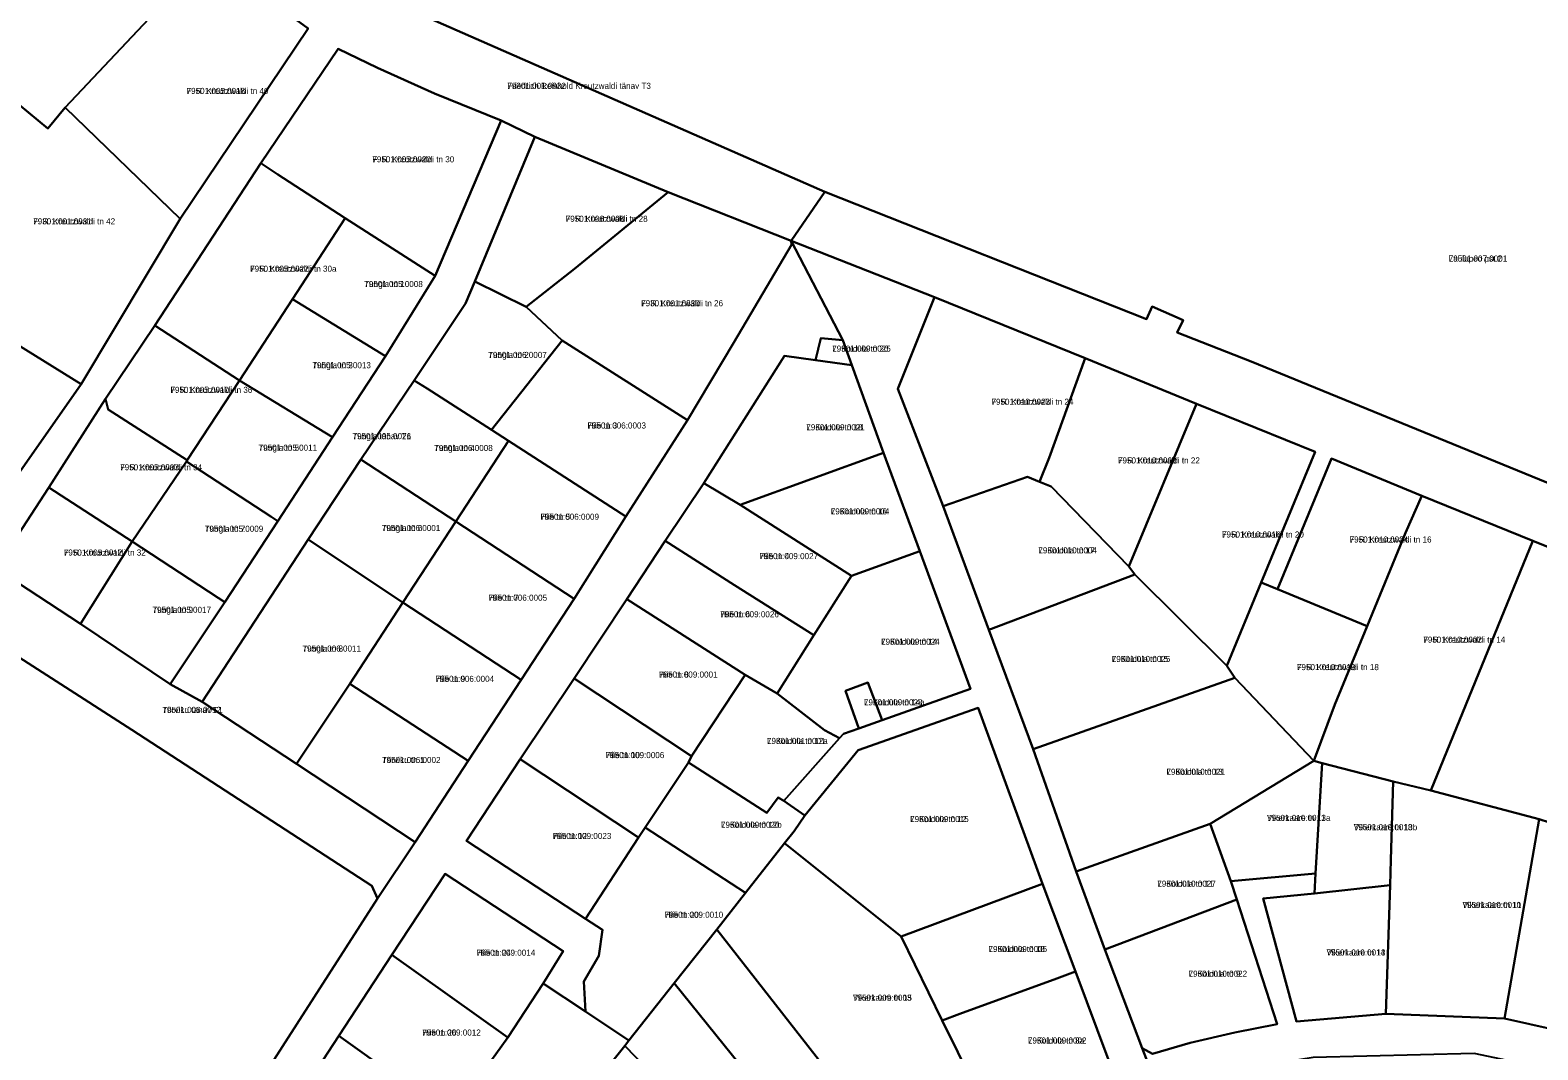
# Model space of a CAD drawing. Extents: x 643847 to 663718, y 6468443 to 6482775.
# Drawn here: x 657706.6 to 658080, y 6474676.3 to 6474928.9 of the extents above; entities that cross this region are included whole.
import ezdxf

# ---------------------------------------------------------------- set-up
doc = ezdxf.new("R2010")
doc.units = 0
for name, color, linetype in [('L_AADRESS', 7, 'Continuous'), ('PIIR', 7, 'Continuous'), ('TUNNUS', 7, 'Continuous')]:
    doc.layers.add(name, color=color, linetype=linetype)

msp = doc.modelspace()

# ---------------------------------------------------------------- linework, layer by layer
at = {"layer": 'PIIR'}
for points in [[(658368.95, 6474713.1), (658360.66, 6474702.37), (658267.33, 6474740.81), (658142.75, 6474792.04), (658009.02, 6474846.81), (657990.7, 6474854.01), (657992.16, 6474857.05), (657984.47, 6474860.4), (657983.07, 6474857.31), (657903.43, 6474888.85), (657797.5, 6474935.34), (657789.25, 6474936.69), (657954.47, 6475040.78), (658054.62, 6474961.35), (658120.68, 6474909.93), (658236.64, 6474817.54)], [(657657.15, 6474928.51), (657631.83, 6474952.27), (657635.14, 6474954.7), (657640.69, 6474958.88), (657651.21, 6474965.02), (657664.12, 6474971.48), (657667.65, 6474973.25), (657692.56, 6474996.42), (657695.37, 6474997.08), (657698.35, 6474996.6), (657712.52, 6474987.7), (657751.18, 6474947.87), (657715.23, 6474909.77), (657710.96, 6474904.51), (657691.74, 6474920.38), (657684.32, 6474903.66), (657681.91, 6474905.58)], [(657753.83, 6474945.17), (657775.42, 6474929.36), (657743.72, 6474882.17), (657715.23, 6474909.77), (657751.18, 6474947.87)], [(657782.86, 6474924.32), (657792.63, 6474919.61), (657806.7, 6474913.25), (657823.21, 6474906.52), (657806.88, 6474868.01), (657784.64, 6474882.35), (657775.21, 6474888.43), (657767.93, 6474893.13), (657763.7, 6474895.95)], [(657715.23, 6474909.77), (657743.72, 6474882.17), (657719.23, 6474841.21), (657668.42, 6474872.63), (657681.91, 6474905.58), (657684.32, 6474903.66), (657691.74, 6474920.38), (657710.96, 6474904.51)], [(657806.88, 6474868.01), (657823.21, 6474906.52), (657831.55, 6474902.47), (657816.68, 6474866.66), (657814.4, 6474861.17), (657801.72, 6474842.12), (657788.45, 6474822.54), (657775.46, 6474802.68), (657749.17, 6474762.49), (657741.29, 6474766.89), (657754.78, 6474787.19), (657767.89, 6474807.29), (657781.43, 6474828.06), (657794.55, 6474848.17)], [(657829.46, 6474860.39), (657816.68, 6474866.66), (657831.55, 6474902.47), (657864.58, 6474888.75), (657841.43, 6474869.77)], [(657763.7, 6474895.95), (657767.93, 6474893.13), (657775.21, 6474888.43), (657784.64, 6474882.35), (657771.52, 6474862.25), (657758.4, 6474842.14), (657737.47, 6474855.75)], [(657841.43, 6474869.77), (657864.58, 6474888.75), (657895.09, 6474876.69), (657895.12, 6474875.76), (657880.89, 6474851.48), (657869.4, 6474832.27), (657838.35, 6474852.04), (657829.46, 6474860.39)], [(657794.55, 6474848.17), (657771.52, 6474862.25), (657784.64, 6474882.35), (657806.88, 6474868.01)], [(657690.64, 6474800.49), (657682.76, 6474805.73), (657644.4, 6474800.63), (657637.48, 6474852.67), (657668.42, 6474872.63), (657719.23, 6474841.21)], [(657814.4, 6474861.17), (657816.68, 6474866.66), (657829.46, 6474860.39), (657838.35, 6474852.04), (657820.86, 6474829.86), (657804.88, 6474840.1), (657801.72, 6474842.12)], [(657967.91, 6474847.62), (657959.01, 6474822.92), (657956.55, 6474817.03), (657953.62, 6474818.24), (657932.75, 6474810.97), (657921.48, 6474840), (657930.59, 6474862.78)], [(657781.43, 6474828.06), (657758.4, 6474842.14), (657771.52, 6474862.25), (657794.55, 6474848.17)], [(657737.47, 6474855.75), (657758.4, 6474842.14), (657745.49, 6474822.33), (657725.89, 6474834.9), (657725.25, 6474837.53)], [(657854.12, 6474808.39), (657825.08, 6474827.17), (657820.86, 6474829.86), (657838.35, 6474852.04), (657869.4, 6474832.27)], [(657902.39, 6474852.63), (657907.85, 6474852.06), (657910.12, 6474845.89), (657901.07, 6474847.15)], [(657917.96, 6474824.17), (657882.4, 6474811.33), (657873.42, 6474816.68), (657893.39, 6474848.24), (657901.07, 6474847.15), (657910.12, 6474845.89)], [(657995.48, 6474836.36), (657978.72, 6474796.01), (657959.48, 6474815.81), (657956.55, 6474817.03), (657959.01, 6474822.92), (657967.91, 6474847.62)], [(657767.89, 6474807.29), (657766.22, 6474808.38), (657745.29, 6474822.04), (657745.49, 6474822.33), (657758.4, 6474842.14), (657781.43, 6474828.06)], [(657801.72, 6474842.12), (657804.88, 6474840.1), (657820.86, 6474829.86), (657825.08, 6474827.17), (657812.02, 6474807.16), (657788.45, 6474822.54)], [(657711.22, 6474815.61), (657725.25, 6474837.53), (657725.89, 6474834.9), (657745.49, 6474822.33), (657745.29, 6474822.04), (657731.82, 6474802.19)], [(657995.48, 6474836.36), (658024.82, 6474824.43), (658011.47, 6474792.07), (658002.95, 6474771.42), (657980.22, 6474794.01), (657978.72, 6474796.01)], [(657841.32, 6474788.03), (657812.02, 6474807.16), (657825.08, 6474827.17), (657854.12, 6474808.39)], [(657754.78, 6474787.19), (657753.11, 6474788.28), (657731.82, 6474802.19), (657745.29, 6474822.04), (657766.22, 6474808.38), (657767.89, 6474807.29)], [(657788.45, 6474822.54), (657812.02, 6474807.16), (657798.89, 6474787.06), (657775.46, 6474802.68)], [(657926.97, 6474799.81), (657910, 6474793.69), (657882.4, 6474811.33), (657917.96, 6474824.17)], [(658051.24, 6474813.54), (658047.26, 6474804.34), (658037.72, 6474781.23), (658015.53, 6474790.39), (658028.88, 6474822.75)], [(657932.75, 6474810.97), (657953.62, 6474818.24), (657956.55, 6474817.03), (657959.48, 6474815.81), (657978.72, 6474796.01), (657980.22, 6474794.01), (657944.02, 6474780.31)], [(657711.22, 6474815.61), (657731.82, 6474802.19), (657719.04, 6474781.84), (657698.09, 6474795.51)], [(657863.88, 6474802.34), (657873.42, 6474816.68), (657882.4, 6474811.33), (657910, 6474793.69), (657900.72, 6474779), (657881.03, 6474791.38), (657871.83, 6474797.29)], [(658078.76, 6474802.34), (658053.51, 6474740.48), (658044.18, 6474742.72), (658026.62, 6474747.31), (658024.52, 6474747.88), (658029.7, 6474761.8), (658037.72, 6474781.23), (658047.26, 6474804.34), (658051.24, 6474813.54)], [(657828.2, 6474767.93), (657798.89, 6474787.06), (657812.02, 6474807.16), (657841.32, 6474788.03)], [(657801.97, 6474727.72), (657792.61, 6474713.76), (657791.23, 6474716.92), (657731.79, 6474755.58), (657674.33, 6474792.51), (657645.98, 6474788.74), (657566.4, 6474778.14), (657565.29, 6474786.3), (657644.93, 6474796.66), (657644.4, 6474800.63), (657682.76, 6474805.73), (657690.64, 6474800.49), (657698.09, 6474795.51), (657719.04, 6474781.84), (657741.29, 6474766.89), (657749.17, 6474762.49), (657772.52, 6474747.12)], [(657741.29, 6474766.89), (657719.04, 6474781.84), (657731.82, 6474802.19), (657753.11, 6474788.28), (657754.78, 6474787.19)], [(657749.17, 6474762.49), (657775.46, 6474802.68), (657798.89, 6474787.06), (657785.78, 6474766.96), (657772.52, 6474747.12)], [(657863.88, 6474802.34), (657871.83, 6474797.29), (657881.03, 6474791.38), (657900.72, 6474779), (657891.62, 6474764.54), (657883.64, 6474769.14), (657854.38, 6474787.94)], [(657926.97, 6474799.81), (657939.46, 6474765.69), (657917.64, 6474757.95), (657914.02, 6474767.28), (657908.55, 6474765.21), (657911.85, 6474755.87), (657908.07, 6474754.58), (657907.02, 6474753.49), (657903.29, 6474755.49), (657891.62, 6474764.54), (657900.72, 6474779), (657910, 6474793.69)], [(658106.56, 6474791.26), (658082.9, 6474732.57), (658080.32, 6474733.4), (658053.51, 6474740.48), (658078.76, 6474802.34)], [(657792.61, 6474713.76), (657685.52, 6474547), (657625.76, 6474585.87), (657621.21, 6474620.11), (657588, 6474615.68), (657566.4, 6474778.14), (657645.98, 6474788.74), (657674.33, 6474792.51), (657731.79, 6474755.58), (657791.23, 6474716.92)], [(657944.02, 6474780.31), (657980.22, 6474794.01), (658002.95, 6474771.42), (658004.95, 6474768.4), (657954.99, 6474750.73)], [(658015.53, 6474790.39), (658037.72, 6474781.23), (658029.7, 6474761.8), (658024.52, 6474747.88), (658004.95, 6474768.4), (658002.95, 6474771.42), (658011.47, 6474792.07)], [(657815.09, 6474747.83), (657785.78, 6474766.96), (657798.89, 6474787.06), (657828.2, 6474767.93)], [(657854.38, 6474787.94), (657883.64, 6474769.14), (657870.41, 6474749.05), (657841.29, 6474768.23)], [(657772.52, 6474747.12), (657785.78, 6474766.96), (657815.09, 6474747.83), (657801.97, 6474727.72)], [(657841.29, 6474768.23), (657870.41, 6474749.05), (657869.61, 6474747.42), (657858.9, 6474731.35), (657857.26, 6474728.84), (657827.95, 6474748.27)], [(657870.41, 6474749.05), (657883.64, 6474769.14), (657891.62, 6474764.54), (657903.29, 6474755.49), (657907.02, 6474753.49), (657893.25, 6474737.94), (657891.87, 6474738.81), (657889.03, 6474734.98), (657869.61, 6474747.42)], [(657917.64, 6474757.95), (657911.85, 6474755.87), (657908.55, 6474765.21), (657914.02, 6474767.28)], [(657954.99, 6474750.73), (658004.95, 6474768.4), (658024.52, 6474747.88), (657998.88, 6474732.25), (657965.68, 6474720.42)], [(657957.36, 6474717.42), (657922.35, 6474704.37), (657893.43, 6474727.47), (657895.78, 6474730.48), (657898.45, 6474734.34), (657911.63, 6474750.5), (657941.37, 6474761.01)], [(657857.26, 6474728.84), (657844.13, 6474708.75), (657814.68, 6474728.01), (657827.95, 6474748.27)], [(657898.45, 6474734.34), (657895.78, 6474730.48), (657893.43, 6474727.47), (657883.74, 6474715.13), (657858.9, 6474731.35), (657869.61, 6474747.42), (657889.03, 6474734.98), (657891.87, 6474738.81), (657893.25, 6474737.94)], [(658003.98, 6474718.09), (657998.88, 6474732.25), (658024.52, 6474747.88), (658026.62, 6474747.31), (658024.97, 6474719.99)], [(658024.97, 6474719.99), (658026.62, 6474747.31), (658044.18, 6474742.72), (658043.59, 6474723.37), (658043.39, 6474717.09), (658024.66, 6474715.01)], [(658042.36, 6474685.2), (658043.39, 6474717.09), (658043.59, 6474723.37), (658044.18, 6474742.72), (658053.51, 6474740.48), (658080.32, 6474733.4), (658071.76, 6474684.01)], [(657972.79, 6474701.12), (657965.68, 6474720.42), (657998.88, 6474732.25), (658003.98, 6474718.09), (658005.47, 6474713.48)], [(658080.32, 6474733.4), (658082.9, 6474732.57), (658111.55, 6474725.08), (658102.36, 6474677.14), (658071.76, 6474684.01)], [(657844.14, 6474685.73), (657843.71, 6474693.17), (657847.4, 6474699.56), (657848.31, 6474706.02), (657844.13, 6474708.75), (657857.26, 6474728.84), (657858.9, 6474731.35), (657883.74, 6474715.13), (657876.64, 6474706.08), (657866.09, 6474692.75), (657854.86, 6474678.55)], [(657922.29, 6474647.68), (657876.64, 6474706.08), (657883.74, 6474715.13), (657893.43, 6474727.47), (657922.35, 6474704.37), (657932.47, 6474683.57), (657944.1, 6474659.99)], [(657809.33, 6474719.84), (657838.62, 6474700.69), (657833.67, 6474692.74), (657824.92, 6474679.34), (657796.18, 6474699.77)], [(657957.36, 6474717.42), (657965.47, 6474695.67), (657960.87, 6474693.91), (657936.82, 6474685.15), (657932.47, 6474683.57), (657922.35, 6474704.37)], [(658020.26, 6474683.3), (658011.95, 6474713.8), (658024.66, 6474715.01), (658043.39, 6474717.09), (658042.36, 6474685.2)], [(657972.79, 6474701.12), (658005.47, 6474713.48), (658015.48, 6474682.6), (658004.95, 6474680.59), (657993.86, 6474678.04), (657984.59, 6474675.28), (657982.01, 6474676.66)], [(657908.9, 6474638.78), (657903.42, 6474646.9), (657898.16, 6474654.7), (657892.57, 6474659.9), (657866.09, 6474692.75), (657876.64, 6474706.08), (657922.29, 6474647.68)], [(657796.18, 6474699.77), (657824.92, 6474679.34), (657810.89, 6474659.83), (657783.05, 6474679.72)], [(657973.64, 6474673.77), (657972.41, 6474671.29), (657944.1, 6474659.99), (657932.47, 6474683.57), (657936.82, 6474685.15), (657960.87, 6474693.91), (657965.47, 6474695.67)], [(657844.14, 6474685.73), (657854.86, 6474678.55), (657853.83, 6474677.25), (657843.36, 6474664.11), (657833.45, 6474651.69), (657829.4, 6474646.6), (657810.89, 6474659.83), (657824.92, 6474679.34), (657833.67, 6474692.74)], [(657897.86, 6474631.81), (657853.83, 6474677.25), (657854.86, 6474678.55), (657866.09, 6474692.75), (657892.57, 6474659.9), (657898.16, 6474654.7), (657903.42, 6474646.9), (657908.9, 6474638.78)], [(657783.05, 6474679.72), (657810.89, 6474659.83), (657792.79, 6474634.67), (657766.14, 6474653.77)], [(657886.84, 6474622.78), (657880.33, 6474629.12), (657875.63, 6474634.82), (657843.36, 6474664.11), (657853.83, 6474677.25), (657897.86, 6474631.81)]]:
    msp.add_lwpolyline(points, close=True, dxfattribs=at)
for points in [[(657697.41, 6475033.22), (657712.42, 6475017.42), (657721.39, 6475007.99), (657778.7, 6474947.76), (657789.25, 6474936.69), (657797.5, 6474935.34), (657903.43, 6474888.85), (657895.09, 6474876.69), (657864.58, 6474888.75), (657831.55, 6474902.47), (657823.21, 6474906.52), (657806.7, 6474913.25), (657792.63, 6474919.61), (657782.86, 6474924.32), (657763.7, 6474895.95), (657737.47, 6474855.75), (657725.25, 6474837.53), (657711.22, 6474815.61), (657698.09, 6474795.51)], [(657690.64, 6474800.49), (657719.23, 6474841.21), (657743.72, 6474882.17), (657775.42, 6474929.36), (657753.83, 6474945.17), (657751.18, 6474947.87), (657712.52, 6474987.7), (657699.64, 6475001.04)], [(658106.56, 6474791.26), (658078.76, 6474802.34), (658051.24, 6474813.54), (658028.88, 6474822.75), (658015.53, 6474790.39), (658011.47, 6474792.07), (658024.82, 6474824.43), (657995.48, 6474836.36), (657967.91, 6474847.62), (657930.59, 6474862.78), (657895.09, 6474876.69), (657903.43, 6474888.85), (657983.07, 6474857.31), (657984.47, 6474860.4), (657992.16, 6474857.05), (657990.7, 6474854.01), (658009.02, 6474846.81), (658142.75, 6474792.04)], [(657685.52, 6474547), (657792.61, 6474713.76), (657801.97, 6474727.72), (657815.09, 6474747.83), (657828.2, 6474767.93), (657841.32, 6474788.03), (657854.12, 6474808.39), (657869.4, 6474832.27), (657880.89, 6474851.48), (657895.12, 6474875.76), (657895.09, 6474876.69), (657907.85, 6474852.06), (657902.39, 6474852.63), (657901.07, 6474847.15), (657893.39, 6474848.24), (657873.42, 6474816.68), (657863.88, 6474802.34), (657854.38, 6474787.94), (657841.29, 6474768.23), (657827.95, 6474748.27), (657814.68, 6474728.01), (657844.13, 6474708.75), (657848.31, 6474706.02), (657847.4, 6474699.56), (657843.71, 6474693.17), (657844.14, 6474685.73), (657833.67, 6474692.74), (657838.62, 6474700.69), (657809.33, 6474719.84), (657796.18, 6474699.77), (657783.05, 6474679.72), (657766.14, 6474653.77)], [(657973.64, 6474673.77), (657965.47, 6474695.67), (657957.36, 6474717.42), (657941.37, 6474761.01), (657911.63, 6474750.5), (657898.42, 6474734.31), (657893.25, 6474737.94), (657907.02, 6474753.49), (657908.07, 6474754.58), (657911.85, 6474755.87), (657917.64, 6474757.95), (657939.46, 6474765.69), (657926.97, 6474799.81), (657917.96, 6474824.17), (657910.12, 6474845.89), (657907.85, 6474852.06), (657895.09, 6474876.69), (657930.59, 6474862.78), (657921.48, 6474840), (657932.75, 6474810.97), (657944.02, 6474780.31), (657954.99, 6474750.73), (657965.68, 6474720.42), (657972.79, 6474701.12), (657982.01, 6474676.66), (657986.75, 6474664.56)], [(658103.87, 6474667), (658064.25, 6474675.38), (658024.35, 6474674.36), (657998.92, 6474670.23), (657988.84, 6474667.39), (657987.37, 6474666.23), (657986.75, 6474664.56), (657982.01, 6474676.66), (657984.59, 6474675.28), (657993.86, 6474678.04), (658004.95, 6474680.59), (658015.48, 6474682.6), (658005.47, 6474713.48), (658003.98, 6474718.09), (658024.97, 6474719.99), (658024.66, 6474715.01), (658011.95, 6474713.8), (658020.26, 6474683.3), (658042.36, 6474685.2), (658071.76, 6474684.01), (658102.36, 6474677.14)]]:
    msp.add_lwpolyline(points, dxfattribs=at)

# ---------------------------------------------------------------- texts
at = {"layer": 'L_AADRESS'}
for s, p in [('Friedrich Reinhold Kreutzwaldi tänav T3', (657824.76, 6474914.37)), ('F. R. Kreutzwaldi tn 40', (657745.32, 6474913.11)), ('F. R. Kreutzwaldi tn 30', (657791.33, 6474896.17)), ('F. R. Kreutzwaldi tn 42', (657707.33, 6474880.79)), ('F. R. Kreutzwaldi tn 28', (657839.23, 6474881.43)), ('F. R. Kreutzwaldi tn 30a', (657761.05, 6474869.05)), ('Laulupeo pst 2', (658057.94, 6474871.58)), ('Tungla tn 1', (657789.33, 6474865.26)), ('F. R. Kreutzwaldi tn 26', (657857.9, 6474860.51)), ('Tungla tn 2', (657820.04, 6474847.7)), ('L. Koidula tn 20', (657905.23, 6474849.26)), ('Tungla tn 3', (657776.47, 6474845.15)), ('F. R. Kreutzwaldi tn 36', (657741.32, 6474839.04)), ('F. R. Kreutzwaldi tn 24', (657944.69, 6474836.09)), ('Tungla tänav T1', (657786.42, 6474827.57)), ('Hiie tn 3', (657844.61, 6474830.21)), ('L. Koidula tn 18', (657898.82, 6474829.78)), ('Tungla tn 5', (657763.15, 6474824.71)), ('Tungla tn 4', (657806.65, 6474824.64)), ('F. R. Kreutzwaldi tn 22', (657976.01, 6474821.55)), ('F. R. Kreutzwaldi tn 34', (657728.88, 6474819.86)), ('L. Koidula tn 16', (657904.88, 6474808.93)), ('Hiie tn 5', (657832.97, 6474807.6)), ('Tungla tn 7', (657749.81, 6474804.62)), ('Tungla tn 6', (657793.66, 6474804.8)), ('F. R. Kreutzwaldi tn 20', (658001.77, 6474803.2)), ('F. R. Kreutzwaldi tn 16', (658033.39, 6474801.96)), ('F. R. Kreutzwaldi tn 32', (657714.92, 6474798.73)), ('Hiie tn 4', (657887.24, 6474797.84)), ('L. Koidula tn 17', (657956.3, 6474799.27)), ('Hiie tn 7', (657820.11, 6474787.54)), ('Tungla tn 9', (657736.88, 6474784.54)), ('Hiie tn 6', (657877.52, 6474783.44)), ('L. Koidula tn 14', (657917.34, 6474776.65)), ('F. R. Kreutzwaldi tn 14', (658051.64, 6474777.15)), ('Tungla tn 8', (657774.03, 6474774.94)), ('L. Koidula tn 15', (657974.48, 6474772.37)), ('Hiie tn 8', (657862.34, 6474768.5)), ('F. R. Kreutzwaldi tn 18', (658020.34, 6474770.34)), ('Hiie tn 9', (657806.99, 6474767.44)), ('L. Koidula tn 14a', (657913.09, 6474761.62)), ('Tõrviku tänav T1', (657739.32, 6474759.75)), ('L. Koidula tn 12a', (657889.07, 6474752.06)), ('Tõrviku tn 1', (657793.72, 6474747.34)), ('Hiie tn 10', (657849.14, 6474748.54)), ('L. Koidula tn 13', (657988.02, 6474744.41)), ('L. Koidula tn 12b', (657877.67, 6474731.28)), ('L. Koidula tn 12', (657924.53, 6474732.69)), ('Vikerkaare tn 13a', (658012.92, 6474732.99)), ('Vikerkaare tn 13b', (658034.42, 6474730.68)), ('Hiie tn 12', (657836.03, 6474728.51)), ('L. Koidula tn 11', (657985.75, 6474716.69)), ('Hiie tn 20', (657863.73, 6474708.98)), ('Vikerkaare tn 11', (658061.34, 6474711.42)), ('Hiie tn 24', (657817.18, 6474699.59)), ('L. Koidula tn 10', (657943.95, 6474700.5)), ('Vikerkaare tn 13', (658027.67, 6474699.64)), ('L. Koidula tn 9', (657993.5, 6474694.38)), ('Vikerkaare tn 15', (657910.37, 6474688.43)), ('Hiie tn 26', (657803.69, 6474679.8)), ('L. Koidula tn 8a', (657953.71, 6474677.83))]:
    msp.add_text(s, height=1.5, dxfattribs=at).set_placement(p)
at = {"layer": 'TUNNUS'}
for s, p in [('79301:001:0932', (657824.76, 6474914.37)), ('79501:005:0018', (657745.32, 6474913.11)), ('79501:005:0020', (657791.33, 6474896.17)), ('79301:001:0931', (657707.33, 6474880.79)), ('79501:006:0006', (657839.23, 6474881.43)), ('79501:005:0022', (657761.05, 6474869.05)), ('79501:007:0001', (658057.94, 6474871.58)), ('79501:005:0008', (657789.33, 6474865.26)), ('79301:001:0830', (657857.9, 6474860.51)), ('79501:006:0007', (657820.04, 6474847.7)), ('79501:009:0025', (657905.23, 6474849.26)), ('79501:005:0013', (657776.47, 6474845.15)), ('79501:005:0010', (657741.32, 6474839.04)), ('79501:010:0023', (657944.69, 6474836.09)), ('79501:006:0003', (657844.61, 6474830.21)), ('79501:009:0021', (657898.82, 6474829.78)), ('79501:005:0011', (657763.15, 6474824.71)), ('79501:005:0026', (657786.42, 6474827.57)), ('79501:006:0008', (657806.65, 6474824.64)), ('79501:010:0008', (657976.01, 6474821.55)), ('79501:005:0003', (657728.88, 6474819.86)), ('79501:009:0004', (657904.88, 6474808.93)), ('79501:006:0009', (657832.97, 6474807.6)), ('79501:005:0009', (657749.81, 6474804.62)), ('79501:006:0001', (657793.66, 6474804.8)), ('79501:010:0016', (658001.77, 6474803.2)), ('79501:010:0024', (658033.39, 6474801.96)), ('79501:005:0012', (657714.92, 6474798.73)), ('79501:009:0027', (657887.24, 6474797.84)), ('79501:010:0004', (657956.3, 6474799.27)), ('79501:006:0005', (657820.11, 6474787.54)), ('79501:005:0017', (657736.88, 6474784.54)), ('79501:009:0026', (657877.52, 6474783.44)), ('79501:009:0024', (657917.34, 6474776.65)), ('79501:010:0002', (658051.64, 6474777.15)), ('79501:006:0011', (657774.03, 6474774.94)), ('79501:010:0025', (657974.48, 6474772.37)), ('79501:009:0001', (657862.34, 6474768.5)), ('79501:010:0019', (658020.34, 6474770.34)), ('79501:006:0004', (657806.99, 6474767.44)), ('79501:009:0028', (657913.09, 6474761.62)), ('79501:006:0012', (657739.32, 6474759.75)), ('79301:001:0001', (657889.07, 6474752.06)), ('79501:006:0002', (657793.72, 6474747.34)), ('79501:009:0006', (657849.14, 6474748.54)), ('79501:010:0021', (657988.02, 6474744.41)), ('79501:009:0020', (657877.67, 6474731.28)), ('79501:009:0015', (657924.53, 6474732.69)), ('79501:010:0011', (658012.92, 6474732.99)), ('79501:010:0018', (658034.42, 6474730.68)), ('79501:009:0023', (657836.03, 6474728.51)), ('79501:010:0027', (657985.75, 6474716.69)), ('79501:009:0010', (657863.73, 6474708.98)), ('79501:010:0010', (658061.34, 6474711.42)), ('79501:009:0014', (657817.18, 6474699.59)), ('79501:009:0005', (657943.95, 6474700.5)), ('79501:010:0014', (658027.67, 6474699.64)), ('79501:010:0022', (657993.5, 6474694.38)), ('79501:009:0003', (657910.37, 6474688.43)), ('79501:009:0012', (657803.69, 6474679.8)), ('79501:009:0002', (657953.71, 6474677.83))]:
    msp.add_text(s, height=1.5, dxfattribs=at).set_placement(p)

doc.saveas('drawing.dxf')
